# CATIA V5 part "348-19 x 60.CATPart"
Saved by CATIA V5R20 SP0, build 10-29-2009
Part number: 348-19 x 60
Definition: NONE
Nomenclature: 348-19 x 60
Source: Unknown
Description: 348-19 x 60
Bounding box of the stored display mesh (mm): x 0 to 60, y -15 to 15, z -15 to 15
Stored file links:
  C:\Users\Utente\Desktop\IO LAVORO\3D X SITO CF\X SITO\3D files 348\348-19 x 60.CATPart
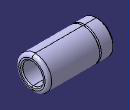
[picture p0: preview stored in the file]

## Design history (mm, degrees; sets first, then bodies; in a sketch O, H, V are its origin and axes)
Body1 "348-19 x 60" (main body)
  Solid1: solid without history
